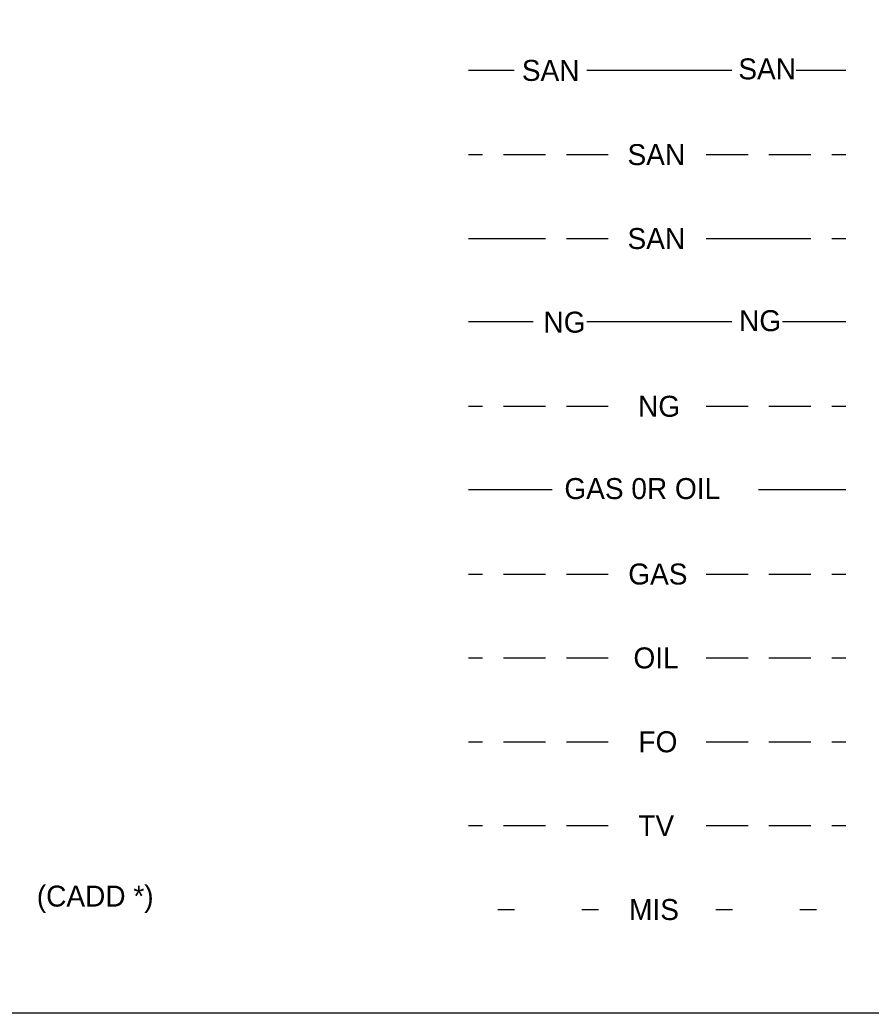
# Model space of a CAD drawing. Extents: x 49991.4 to 50021, y 49987.6 to 50011.4.
# Drawn here: x 50007.009 to 50009.446, y 49987.799 to 49990.641 of the extents above; entities that cross this region are included whole.
import ezdxf

# ---------------------------------------------------------------- set-up
doc = ezdxf.new("R2010")
doc.units = 0
doc.layers.add('Level 1', color=7, linetype='Continuous')
doc.layers.add('Level 2', color=7, linetype='Continuous')

msp = doc.modelspace()

# ---------------------------------------------------------------- linework, layer by layer
at = {"layer": 'Level 1'}
for p, q in [((50008.2935, 49990.4973), (50008.4238, 49990.4973)), ((50008.6317, 49990.4973), (50009.0475, 49990.4973)), ((50009.2314, 49990.4973), (50009.3735, 49990.4973)), ((50008.2935, 49990.2552), (50008.3335, 49990.2552)), ((50008.3935, 49990.2552), (50008.5135, 49990.2552)), ((50008.5735, 49990.2552), (50008.6935, 49990.2552)), ((50008.9735, 49990.2552), (50009.0935, 49990.2552)), ((50009.1535, 49990.2552), (50009.2735, 49990.2552)), ((50009.3335, 49990.2552), (50009.3735, 49990.2552)), ((50008.2935, 49990.0151), (50008.5136, 49990.0151)), ((50008.5736, 49990.0151), (50008.6936, 49990.0151)), ((50008.9736, 49990.0151), (50009.2736, 49990.0151)), ((50009.3336, 49990.0151), (50009.3735, 49990.0151)), ((50008.2935, 49989.7773), (50008.4782, 49989.7773)), ((50008.6317, 49989.7773), (50009.0475, 49989.7773)), ((50009.1919, 49989.7773), (50009.3735, 49989.7773)), ((50008.2935, 49989.5352), (50008.3335, 49989.5352)), ((50008.3935, 49989.5352), (50008.5135, 49989.5352)), ((50008.5735, 49989.5352), (50008.6935, 49989.5352)), ((50008.9735, 49989.5352), (50009.0935, 49989.5352)), ((50009.1535, 49989.5352), (50009.2735, 49989.5352)), ((50009.3335, 49989.5352), (50009.3735, 49989.5352)), ((50008.2935, 49989.2973), (50008.5327, 49989.2973)), ((50009.1235, 49989.2973), (50009.3735, 49989.2973)), ((50008.2935, 49989.0552), (50008.3335, 49989.0552)), ((50008.3935, 49989.0552), (50008.5135, 49989.0552)), ((50008.5735, 49989.0552), (50008.6935, 49989.0552)), ((50008.9735, 49989.0552), (50009.0935, 49989.0552)), ((50009.1535, 49989.0552), (50009.2735, 49989.0552)), ((50009.3335, 49989.0552), (50009.3735, 49989.0552)), ((50008.2935, 49988.8152), (50008.3335, 49988.8152)), ((50008.3935, 49988.8152), (50008.5135, 49988.8152)), ((50008.5735, 49988.8152), (50008.6935, 49988.8152)), ((50008.9735, 49988.8152), (50009.0935, 49988.8152)), ((50009.1535, 49988.8152), (50009.2735, 49988.8152)), ((50009.3335, 49988.8152), (50009.3735, 49988.8152)), ((50008.2935, 49988.5752), (50008.3335, 49988.5752)), ((50008.3935, 49988.5752), (50008.5135, 49988.5752)), ((50008.5735, 49988.5752), (50008.6935, 49988.5752)), ((50008.9735, 49988.5752), (50009.0935, 49988.5752)), ((50009.1535, 49988.5752), (50009.2735, 49988.5752)), ((50009.3335, 49988.5752), (50009.3735, 49988.5752)), ((50008.2935, 49988.3352), (50008.3335, 49988.3352)), ((50008.3935, 49988.3352), (50008.5135, 49988.3352)), ((50008.5735, 49988.3352), (50008.6935, 49988.3352)), ((50008.9735, 49988.3352), (50009.0935, 49988.3352)), ((50009.1535, 49988.3352), (50009.2735, 49988.3352)), ((50009.3335, 49988.3352), (50009.3735, 49988.3352)), ((50008.3775, 49988.0952), (50008.4255, 49988.0952)), ((50008.6175, 49988.0952), (50008.6655, 49988.0952)), ((50009.0015, 49988.0952), (50009.0495, 49988.0952)), ((50009.2415, 49988.0952), (50009.2895, 49988.0952))]:
    msp.add_line(p, q, dxfattribs=at)
msp.add_lwpolyline([(49999.3835, 49998.9992), (50016.7501, 49998.9992), (50016.7501, 49987.7988), (49999.3835, 49987.7988)], close=True, dxfattribs=at)

# ---------------------------------------------------------------- texts
at = {"layer": 'Level 2'}
for s, p in [('SAN', (50008.4461, 49990.4662)), ('SAN', (50009.0658, 49990.4705)), ('SAN', (50008.7486, 49990.2252)), ('SAN', (50008.7486, 49989.9851)), ('NG', (50008.5081, 49989.7458)), ('NG', (50009.068, 49989.7501)), ('NG', (50008.7789, 49989.5052)), ('GAS 0R OIL', (50008.5679, 49989.2697)), ('GAS', (50008.7508, 49989.0252)), ('OIL', (50008.7656, 49988.7852)), ('FO', (50008.78, 49988.5452)), ('TV', (50008.7795, 49988.3052)), ('(CADD *)', (50007.0577, 49988.1037)), ('MIS', (50008.7532, 49988.0652))]:
    msp.add_text(s, height=0.06, dxfattribs=at).set_placement(p)

doc.saveas('drawing.dxf')
